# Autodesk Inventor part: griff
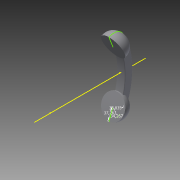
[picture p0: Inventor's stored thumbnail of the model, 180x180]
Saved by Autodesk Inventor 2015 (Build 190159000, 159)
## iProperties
Created: 2014-11
Part Number: griff
Material: Generisch
Document SubType Name: Modeling
Designer: Andreas
Density: 1 g/cm^3
Appearance: Vorgabe
Author: Andreas
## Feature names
1. Sweeping1
2. Umdrehung1 [Revolution]
3. Umdrehung2 [Revolution]
## Parameters: d14 = 3 mm, d15 = 3 mm, d16 = 5 mm, d17 = 5 mm, d18 = 15 mm, d19 = 24 mm, d20 = 25 mm, d21 = 25 mm, d23 = 0, d24 = 0, d25 = 38.83486 mm, d26 = 37.763 mm, d27 = 34.26653 mm, d28 = 90 deg, d29 = 90 deg
